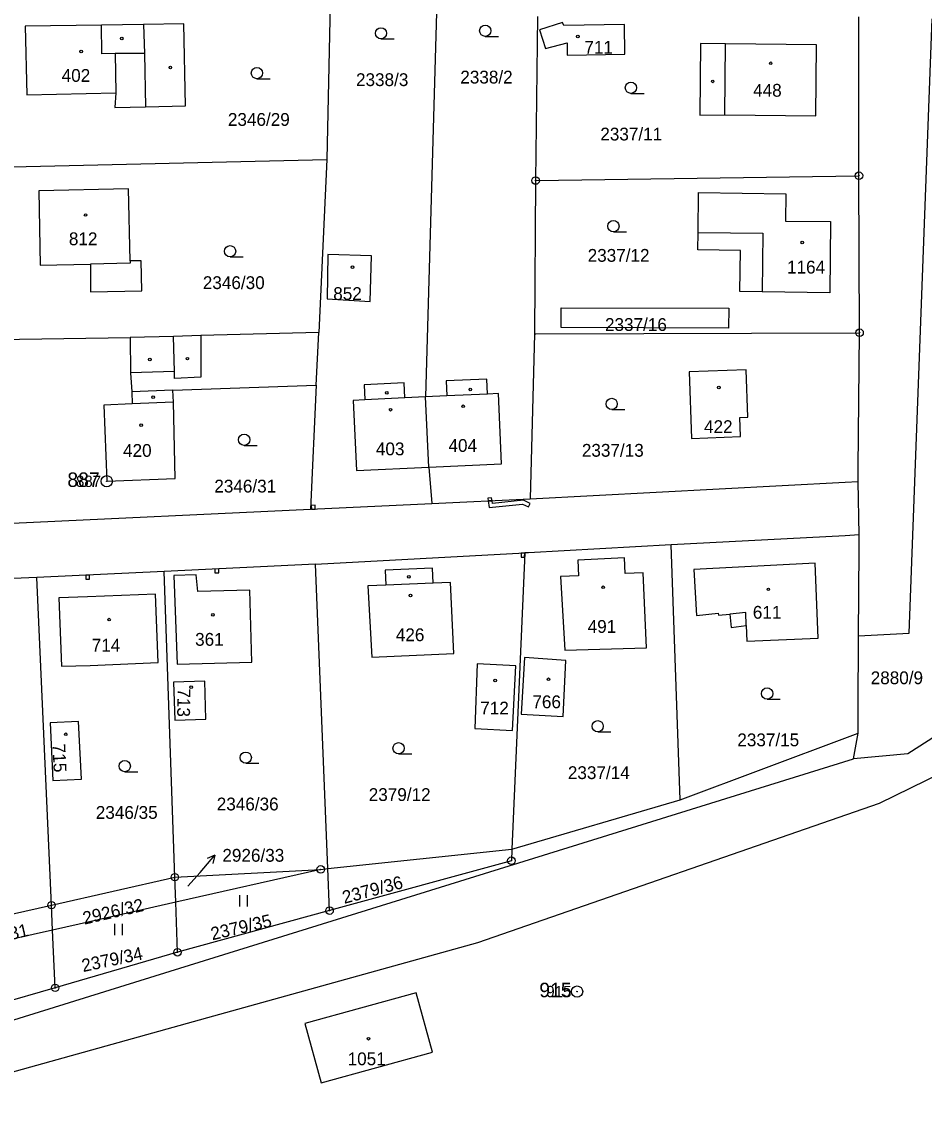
# Model space of a CAD drawing. Extents: x -758836 to -757729, y -1175316 to -1174366.
# Drawn here: x -758709.3 to -758589.5, y -1175013.2 to -1174868.1 of the extents above; entities that cross this region are included whole.
import ezdxf

# ---------------------------------------------------------------- set-up
doc = ezdxf.new("R2010")
doc.units = 0
for name, color, linetype in [('Hranice parcel', 7, 'Continuous'), ('Parcelní čísla', 7, 'Continuous'), ('Pop  PČ popisy', 7, 'Continuous'), ('Vnitřní kresba', 7, 'Continuous'), ('Věcná břemena k části', 7, 'Continuous'), ('Značky bodu BP', 7, 'Continuous'), ('Značky budov', 7, 'Continuous'), ('Značky kultur', 7, 'Continuous')]:
    doc.layers.add(name, color=color, linetype=linetype)

msp = doc.modelspace()

# ---------------------------------------------------------------- linework, layer by layer
at = {"layer": 'Hranice parcel'}
for p, q in [((-758668.33, -1174865.66), (-758668.75, -1174886.35)), ((-758640.8, -1174867.37), (-758641.04, -1174889.13)), ((-758598.11, -1174888.49), (-758598.14, -1174867.4)), ((-758713.31, -1174887.37), (-758668.75, -1174886.35)), ((-758668.75, -1174886.35), (-758669.83, -1174909.28)), ((-758641.04, -1174889.13), (-758598.11, -1174888.49)), ((-758598.03, -1174909.33), (-758598.11, -1174888.49)), ((-758641.04, -1174889.13), (-758641.21, -1174909.49)), ((-758712.85, -1174910.23), (-758694.87, -1174909.97)), ((-758670.16, -1174916.27), (-758669.83, -1174909.28)), ((-758641.21, -1174909.49), (-758641.76, -1174931.39)), ((-758670.16, -1174916.27), (-758670.93, -1174932.75)), ((-758655.2, -1174927.18), (-758655.65, -1174917.85)), ((-758655.2, -1174927.18), (-758654.82, -1174932)), ((-758598.09, -1174936.17), (-758598.23, -1174929.06)), ((-758670.93, -1174932.75), (-758654.82, -1174932)), ((-758654.82, -1174932), (-758641.76, -1174931.39)), ((-758710.56, -1174934.59), (-758670.93, -1174932.75)), ((-758621.85, -1174971.3), (-758623.02, -1174937.49)), ((-758670.27, -1174940.06), (-758642.48, -1174938.55)), ((-758642.48, -1174938.55), (-758644.19, -1174977.86)), ((-758690.37, -1174941.01), (-758707.25, -1174941.82)), ((-758670.27, -1174940.06), (-758690.37, -1174941.01)), ((-758688.94, -1174981.58), (-758690.37, -1174941.01)), ((-758668.63, -1174980.42), (-758670.27, -1174940.06)), ((-758707.25, -1174941.82), (-758724.75, -1174942.54)), ((-758705.32, -1174985.3), (-758707.25, -1174941.82)), ((-758598.85, -1174965.89), (-758598.22, -1174962.46)), ((-758691.55, -1174994.68), (-758598.85, -1174965.89)), ((-758644.19, -1174977.86), (-758621.85, -1174971.3)), ((-758668.63, -1174980.42), (-758644.19, -1174977.86)), ((-758705.32, -1174985.3), (-758688.94, -1174981.58)), ((-758688.94, -1174981.58), (-758669.57, -1174980.55)), ((-758688.82, -1174984.91), (-758688.94, -1174981.58)), ((-758669.57, -1174980.55), (-758688.82, -1174984.91)), ((-758669.57, -1174980.55), (-758668.63, -1174980.42)), ((-758668.4, -1174986.02), (-758668.63, -1174980.42)), ((-758705.17, -1174988.61), (-758705.32, -1174985.3)), ((-758688.82, -1174984.91), (-758701.64, -1174987.81)), ((-758688.59, -1174991.55), (-758688.82, -1174984.91)), ((-758668.4, -1174986.02), (-758688.59, -1174991.55)), ((-758705.17, -1174988.61), (-758722.43, -1174992.51)), ((-758701.64, -1174987.81), (-758705.17, -1174988.61)), ((-758704.83, -1174996.27), (-758705.17, -1174988.61)), ((-758688.59, -1174991.55), (-758704.83, -1174996.27)), ((-758704.83, -1174996.27), (-758722.03, -1175001.26))]:
    msp.add_line(p, q, dxfattribs=at)
for points in [[(-758653.88, -1174850.95), (-758653.85, -1174854.4), (-758655.65, -1174917.85)], [(-758749.71, -1175018.36), (-758683.75, -1175000), (-758648.73, -1174990.25), (-758595.39, -1174971.76), (-758559.83, -1174954.39), (-758554.18, -1174950.69), (-758542.58, -1174943.09), (-758500.14, -1174908.44), (-758460.25, -1174869.94), (-758457.56, -1174867.46)], [(-758698.68, -1174868.49), (-758708.83, -1174868.65), (-758708.6, -1174877.77), (-758696.79, -1174877.47), (-758696.89, -1174879.43), (-758692.82, -1174879.34), (-758687.51, -1174879.21), (-758687.77, -1174868.31), (-758693.09, -1174868.4), (-758698.68, -1174868.49)], [(-758637.45, -1174868.17), (-758640.52, -1174869.12), (-758639.72, -1174871.61), (-758636.84, -1174870.85), (-758636.86, -1174872.5), (-758629.18, -1174872.36), (-758629.25, -1174868.4), (-758637.3, -1174868.55), (-758637.45, -1174868.17)], [(-758598.15, -1174949.55), (-758591.43, -1174949.22), (-758588.38, -1174867.67)], [(-758603.84, -1174880.55), (-758603.74, -1174871.11), (-758615.81, -1174870.99), (-758619.14, -1174870.95), (-758619.24, -1174880.46), (-758615.91, -1174880.43), (-758603.84, -1174880.55)], [(-758694.89, -1174899.8), (-758695.08, -1174890.25), (-758707.02, -1174890.49), (-758706.83, -1174900.34), (-758700.16, -1174900.21), (-758700.14, -1174903.88), (-758693.33, -1174903.77), (-758693.41, -1174899.77), (-758694.89, -1174899.8)], [(-758601.88, -1174894.58), (-758601.96, -1174904.02), (-758610.96, -1174903.89), (-758613.93, -1174903.85), (-758613.85, -1174898.43), (-758619.5, -1174898.34), (-758619.47, -1174896.01), (-758619.43, -1174890.7), (-758607.81, -1174890.89), (-758607.85, -1174894.51), (-758601.88, -1174894.58)], [(-758668.61, -1174898.95), (-758668.71, -1174904.84), (-758663, -1174905.16), (-758662.83, -1174899.11), (-758668.61, -1174898.95)], [(-758637.64, -1174908.65), (-758637.64, -1174906), (-758615.4, -1174906.07), (-758615.45, -1174908.71), (-758637.64, -1174908.65)], [(-758694.87, -1174909.97), (-758694.81, -1174914.65), (-758694.66, -1174917.16), (-758694.6, -1174918.77), (-758698.37, -1174918.92), (-758697.98, -1174929.04), (-758688.92, -1174928.65), (-758689.14, -1174918.56), (-758689.2, -1174916.95), (-758670.16, -1174916.27)], [(-758669.83, -1174909.28), (-758685.48, -1174909.71), (-758689.12, -1174909.81), (-758694.87, -1174909.97)], [(-758641.21, -1174909.49), (-758641.01, -1174909.49), (-758598.03, -1174909.33)], [(-758598.23, -1174929.06), (-758598.22, -1174927.29), (-758598.03, -1174909.33)], [(-758613.07, -1174914.27), (-758620.64, -1174914.53), (-758620.33, -1174923.35), (-758613.83, -1174923.08), (-758613.94, -1174920.59), (-758612.88, -1174920.55), (-758613.07, -1174914.27)], [(-758655.65, -1174917.85), (-758658.41, -1174917.98), (-758658.5, -1174915.99), (-758663.8, -1174916.24), (-758663.71, -1174918.23), (-758665.26, -1174918.3), (-758664.84, -1174927.61), (-758655.2, -1174927.18)], [(-758655.2, -1174927.18), (-758645.56, -1174926.74), (-758645.98, -1174917.4), (-758647.43, -1174917.46), (-758647.52, -1174915.47), (-758652.9, -1174915.73), (-758652.81, -1174917.72), (-758655.65, -1174917.85)], [(-758641.76, -1174931.39), (-758599.94, -1174929.15), (-758598.23, -1174929.06)], [(-758598.09, -1174936.17), (-758599.95, -1174936.27), (-758623.02, -1174937.49)], [(-758598.15, -1174949.55), (-758598.1, -1174938.09), (-758598.09, -1174936.17)], [(-758623.02, -1174937.49), (-758641.98, -1174938.52), (-758642.48, -1174938.55)], [(-758626.32, -1174951.13), (-758626.78, -1174941.18), (-758629.16, -1174941.29), (-758629.26, -1174939.21), (-758635.43, -1174939.5), (-758635.33, -1174941.58), (-758637.72, -1174941.69), (-758637.17, -1174951.44), (-758626.32, -1174951.13)], [(-758660.91, -1174942.83), (-758663.3, -1174942.93), (-758662.78, -1174952.37), (-758651.92, -1174951.89), (-758652.34, -1174942.46), (-758654.63, -1174942.56), (-758654.71, -1174940.56), (-758661, -1174940.83), (-758660.91, -1174942.83)], [(-758603.54, -1174949.88), (-758603.93, -1174939.93), (-758620.02, -1174940.77), (-758619.7, -1174946.86), (-758616.8, -1174946.56), (-758616.77, -1174946.82), (-758615.25, -1174946.66), (-758615.07, -1174948.44), (-758613.08, -1174948.19), (-758613, -1174950.25), (-758603.54, -1174949.88)], [(-758688.65, -1174953.33), (-758678.72, -1174953.05), (-758678.99, -1174943.48), (-758685.89, -1174943.67), (-758686.11, -1174941.45), (-758689.09, -1174941.56), (-758688.65, -1174953.33)], [(-758700.17, -1174953.49), (-758691.15, -1174953.09), (-758691.51, -1174944.02), (-758700.53, -1174944.37), (-758704.36, -1174944.52), (-758704.01, -1174953.58), (-758700.17, -1174953.49)], [(-758556.89, -1174943.02), (-758591.6, -1174965.21), (-758598.85, -1174965.89)], [(-758598.22, -1174962.46), (-758598.2, -1174959.24), (-758598.15, -1174949.55)], [(-758642.97, -1174959.93), (-758637.38, -1174960.24), (-758637.05, -1174952.83), (-758642.52, -1174952.42), (-758642.97, -1174959.93)], [(-758644.09, -1174962.12), (-758643.65, -1174953.54), (-758648.78, -1174953.26), (-758649.12, -1174961.87), (-758644.09, -1174962.12)], [(-758684.98, -1174955.55), (-758689.12, -1174955.68), (-758688.94, -1174960.73), (-758684.83, -1174960.6), (-758684.98, -1174955.55)], [(-758701.73, -1174960.92), (-758705.49, -1174961.08), (-758705.15, -1174968.73), (-758701.35, -1174968.56), (-758701.73, -1174960.92)], [(-758621.85, -1174971.3), (-758599.63, -1174962.98), (-758598.22, -1174962.46)], [(-758644.19, -1174977.86), (-758644.26, -1174979.4), (-758668.4, -1174986.02)], [(-758722.59, -1174989.16), (-758721.71, -1174988.97), (-758705.32, -1174985.3)], [(-758752.46, -1175013.6), (-758691.55, -1174994.68)], [(-758669.52, -1175008.88), (-758654.72, -1175004.79), (-758656.88, -1174996.94), (-758671.67, -1175001), (-758669.52, -1175008.88)]]:
    msp.add_lwpolyline(points, dxfattribs=at)
at = {"layer": 'Pop  PČ popisy'}
for p, q in [((-758685.6, -1174980.94), (-758683.63, -1174978.68)), ((-758683.63, -1174978.68), (-758684.67, -1174979.1)), ((-758683.63, -1174978.68), (-758683.91, -1174979.76)), ((-758687.2, -1174982.78), (-758685.6, -1174980.94))]:
    msp.add_line(p, q, dxfattribs=at)
at = {"layer": 'Vnitřní kresba'}
for p, q in [((-758698.62, -1174872.31), (-758698.68, -1174868.49)), ((-758693.09, -1174868.4), (-758692.99, -1174872.25)), ((-758615.91, -1174880.43), (-758615.81, -1174870.99)), ((-758696.87, -1174872.29), (-758698.62, -1174872.31)), ((-758692.99, -1174872.25), (-758696.87, -1174872.29)), ((-758696.87, -1174872.29), (-758696.79, -1174877.47)), ((-758692.99, -1174872.25), (-758692.82, -1174879.34)), ((-758619.47, -1174896.01), (-758610.85, -1174896.13)), ((-758610.85, -1174896.13), (-758610.96, -1174903.89)), ((-758694.88, -1174900.1), (-758700.16, -1174900.21)), ((-758694.89, -1174899.8), (-758694.88, -1174900.1)), ((-758688.99, -1174914.48), (-758689.12, -1174909.81)), ((-758685.48, -1174909.71), (-758685.51, -1174915.22)), ((-758688.99, -1174914.48), (-758694.81, -1174914.65)), ((-758688.97, -1174915.39), (-758688.99, -1174914.48)), ((-758685.51, -1174915.22), (-758688.97, -1174915.39)), ((-758689.2, -1174916.95), (-758694.66, -1174917.16)), ((-758647.43, -1174917.46), (-758652.81, -1174917.72)), ((-758689.14, -1174918.56), (-758694.6, -1174918.77)), ((-758658.41, -1174917.98), (-758663.71, -1174918.23)), ((-758654.63, -1174942.56), (-758660.91, -1174942.83)), ((-758613.14, -1174946.45), (-758615.25, -1174946.66)), ((-758613.08, -1174948.19), (-758613.14, -1174946.45))]:
    msp.add_line(p, q, dxfattribs=at)
at = {"layer": 'Věcná břemena k části'}
for points in [[(-758670.82, -1174932.25), (-758670.81, -1174932.74), (-758670.31, -1174932.72), (-758670.32, -1174932.23)], [(-758647.33, -1174931.65), (-758646.83, -1174931.63), (-758646.88, -1174931.23), (-758647.38, -1174931.3)], [(-758641.77, -1174932), (-758642.66, -1174931.55), (-758646.78, -1174931.97), (-758646.83, -1174931.63), (-758647.33, -1174931.65), (-758647.2, -1174932.51), (-758642.76, -1174932.07), (-758641.99, -1174932.45)], [(-758642.98, -1174939.09), (-758642.5, -1174939.09), (-758642.48, -1174938.55), (-758642.97, -1174938.57)], [(-758683.12, -1174940.67), (-758683.62, -1174940.69), (-758683.62, -1174941.21), (-758683.12, -1174941.21)], [(-758700.78, -1174941.51), (-758700.75, -1174942.04), (-758700.26, -1174942.02), (-758700.28, -1174941.49)]]:
    msp.add_lwpolyline(points, close=True, dxfattribs=at)
at = {"layer": 'Značky bodu BP'}
for centre, radius in [((-758641.04, -1174889.13), 0.5), ((-758598.11, -1174888.49), 0.5), ((-758598.11, -1174888.49), 0.0303), ((-758641.04, -1174889.13), 0.0303), ((-758598.03, -1174909.33), 0.5), ((-758598.03, -1174909.33), 0.0303), ((-758697.98, -1174929.04), 0.75), ((-758697.98, -1174929.04), 0.03), ((-758669.57, -1174980.55), 0.5), ((-758644.26, -1174979.4), 0.5), ((-758644.26, -1174979.4), 0.0303), ((-758688.94, -1174981.58), 0.5), ((-758688.94, -1174981.58), 0.0303), ((-758669.57, -1174980.55), 0.0303), ((-758705.32, -1174985.3), 0.5), ((-758705.32, -1174985.3), 0.0303), ((-758668.4, -1174986.02), 0.5), ((-758668.4, -1174986.02), 0.0303), ((-758688.59, -1174991.55), 0.5), ((-758688.59, -1174991.55), 0.0303), ((-758704.83, -1174996.27), 0.5), ((-758704.83, -1174996.27), 0.0303), ((-758635.53, -1174996.76), 0.75), ((-758635.53, -1174996.76), 0.03)]:
    msp.add_circle(centre, radius, dxfattribs=at)
at = {"layer": 'Značky budov'}
for centre in [(-758635.44, -1174870.02), (-758696, -1174870.28), (-758701.39, -1174872.01), (-758689.54, -1174874.13), (-758609.83, -1174873.57), (-758617.53, -1174875.97), (-758700.79, -1174893.7), (-758605.63, -1174897.34), (-758665.35, -1174900.62), (-758692.26, -1174912.89), (-758687.28, -1174912.77), (-758616.72, -1174916.59), (-758691.81, -1174917.87), (-758660.81, -1174917.31), (-758649.71, -1174916.85), (-758660.29, -1174919.54), (-758650.65, -1174919.09), (-758693.42, -1174921.59), (-758657.88, -1174941.73), (-758657.64, -1174944.21), (-758632.06, -1174943.11), (-758610.14, -1174943.38), (-758683.88, -1174946.77), (-758697.68, -1174947.4), (-758646.41, -1174955.49), (-758639.33, -1174955.32), (-758686.78, -1174956.37), (-758703.43, -1174962.62), (-758663.22, -1175003.02)]:
    msp.add_circle(centre, 0.175, dxfattribs=at)
at = {"layer": 'Značky kultur'}
for p, q in [((-758647.72, -1174870), (-758645.97, -1174870)), ((-758661.57, -1174870.34), (-758659.82, -1174870.34)), ((-758678.05, -1174875.62), (-758676.3, -1174875.62)), ((-758628.39, -1174877.56), (-758626.64, -1174877.56)), ((-758630.71, -1174895.93), (-758628.96, -1174895.93)), ((-758681.61, -1174899.26), (-758679.86, -1174899.26)), ((-758630.94, -1174919.53), (-758629.19, -1174919.53)), ((-758679.74, -1174924.28), (-758677.99, -1174924.28)), ((-758610.3, -1174957.96), (-758608.55, -1174957.96)), ((-758632.8, -1174962.31), (-758631.05, -1174962.31)), ((-758659.24, -1174965.22), (-758657.49, -1174965.22)), ((-758679.53, -1174966.47), (-758677.78, -1174966.47)), ((-758695.59, -1174967.59), (-758693.84, -1174967.59)), ((-758680.3, -1174985.48), (-758680.3, -1174983.98)), ((-758679.3, -1174985.48), (-758679.3, -1174983.98)), ((-758696.89, -1174989.27), (-758696.89, -1174987.77)), ((-758695.89, -1174989.27), (-758695.89, -1174987.77))]:
    msp.add_line(p, q, dxfattribs=at)
for centre in [(-758647.72, -1174869.25), (-758661.57, -1174869.59), (-758678.05, -1174874.87), (-758628.39, -1174876.81), (-758630.71, -1174895.18), (-758681.61, -1174898.51), (-758630.94, -1174918.78), (-758679.74, -1174923.53), (-758610.3, -1174957.21), (-758632.8, -1174961.56), (-758659.24, -1174964.47), (-758679.53, -1174965.72), (-758695.59, -1174966.84)]:
    msp.add_circle(centre, 0.75, dxfattribs=at)

# ---------------------------------------------------------------- texts
at = {"layer": 'Parcelní čísla'}
for s, p in [('711', (-758634.56, -1174872.29)), ('402', (-758703.97, -1174876.03)), ('2338/3', (-758664.89, -1174876.59)), ('2338/2', (-758651.04, -1174876.25)), ('448', (-758612.16, -1174878)), ('2346/29', (-758681.9, -1174881.87)), ('2337/11', (-758632.45, -1174883.81)), ('812', (-758703.01, -1174897.71)), ('2337/12', (-758634.13, -1174899.91)), ('1164', (-758607.66, -1174901.47)), ('2346/30', (-758685.23, -1174903.53)), ('852', (-758667.91, -1174904.98)), ('2337/16', (-758631.83, -1174909.09)), ('422', (-758618.68, -1174922.64)), ('404', (-758652.61, -1174925.14)), ('420', (-758695.82, -1174925.8)), ('403', (-758662.25, -1174925.59)), ('2337/13', (-758634.9, -1174925.78)), ('2346/31', (-758683.7, -1174930.53)), ('611', (-758612.2, -1174947.28)), ('491', (-758634.13, -1174949.16)), ('361', (-758686.25, -1174950.87)), ('426', (-758659.6, -1174950.26)), ('714', (-758699.98, -1174951.65)), ('2880/9', (-758596.55, -1174955.97)), ('712', (-758648.39, -1174959.99)), ('766', (-758641.47, -1174959.16)), ('2337/15', (-758614.26, -1174964.21)), ('2337/14', (-758636.76, -1174968.56)), ('2379/12', (-758663.2, -1174971.47)), ('2346/36', (-758683.38, -1174972.72)), ('2346/35', (-758699.44, -1174973.84)), ('2926/33', (-758682.63, -1174979.53)), ('1051', (-758666, -1175006.54))]:
    msp.add_text(s, height=1.7, dxfattribs=at).set_placement(p)
for s, rotation, p in [('713', 269, (-758688.57, -1174956.51)), ('715', 273, (-758705.21, -1174963.92)), ('2379/36', 15, (-758666.45, -1174985.13)), ('2926/32', 13, (-758700.96, -1174987.89)), ('2379/35', 13, (-758683.96, -1174989.96)), ('2926/31', 13, (-758716.26, -1174991.21)), ('2379/34', 12, (-758701.12, -1174994.18))]:
    msp.add_text(s, height=1.7, rotation=rotation, dxfattribs=at).set_placement(p)
at = {"layer": 'Značky bodu BP'}
for s, height, p in [('887', 1.919, (-758703.21, -1174929.79)), ('887', 1.5, (-758702.08, -1174929.79)), ('915', 1.919, (-758640.55, -1174997.51)), ('915', 1.5, (-758639.63, -1174997.51))]:
    msp.add_text(s, height=height, dxfattribs=at).set_placement(p)

doc.saveas('drawing.dxf')
